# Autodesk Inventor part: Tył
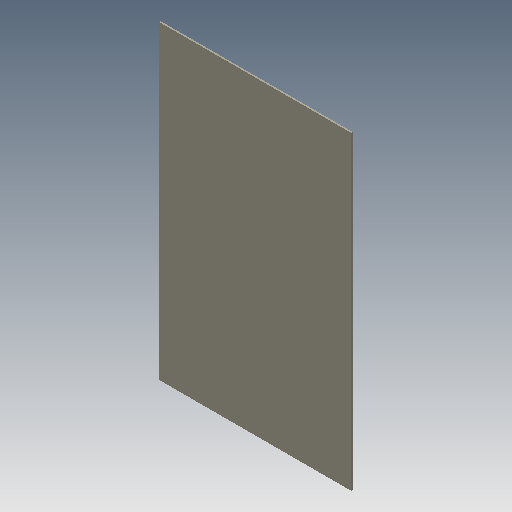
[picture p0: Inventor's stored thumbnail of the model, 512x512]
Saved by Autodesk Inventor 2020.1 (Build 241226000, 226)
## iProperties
Created: 2005-10
Part Number: Tył
Document SubType Name: Modeling
Designer: F.Stasiak
Density: 1 g/cm^3
Material: Ogólny
Appearance: Jasnobeżowa
Manager: www.cadconsulting.pl
Company: Fabian Stasiak CAD Consulting
Author: F.Stasiak
Subject: Zbiór ćwiczeń. Autodesk Inventor 2020. Kurs podstawowy
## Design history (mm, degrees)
sketch "Szkic1"
  geometry: L1 (-456.283, -161.796)-(149.717, -161.796); L2 (149.717, -161.796)-(149.717, 214.204); L3 (149.717, 214.204)-(-456.283, 214.204); L4 (-456.283, 214.204)-(-456.283, -161.796); L5 (-456.283, 26.204)-(149.717, 26.204)
  constraints: 10 end point, 2 midpoint, 2 parallel, 1 horizontal, 1 perpendicular
extrude "Wyciągnięcie proste1" new body sketch "Szkic1" distance "d0" = 3; taper "d1" = 0 deg
node "Bryła1"
node "Korpusy bryłowe"
node "Korpusy powierzchniowe"
